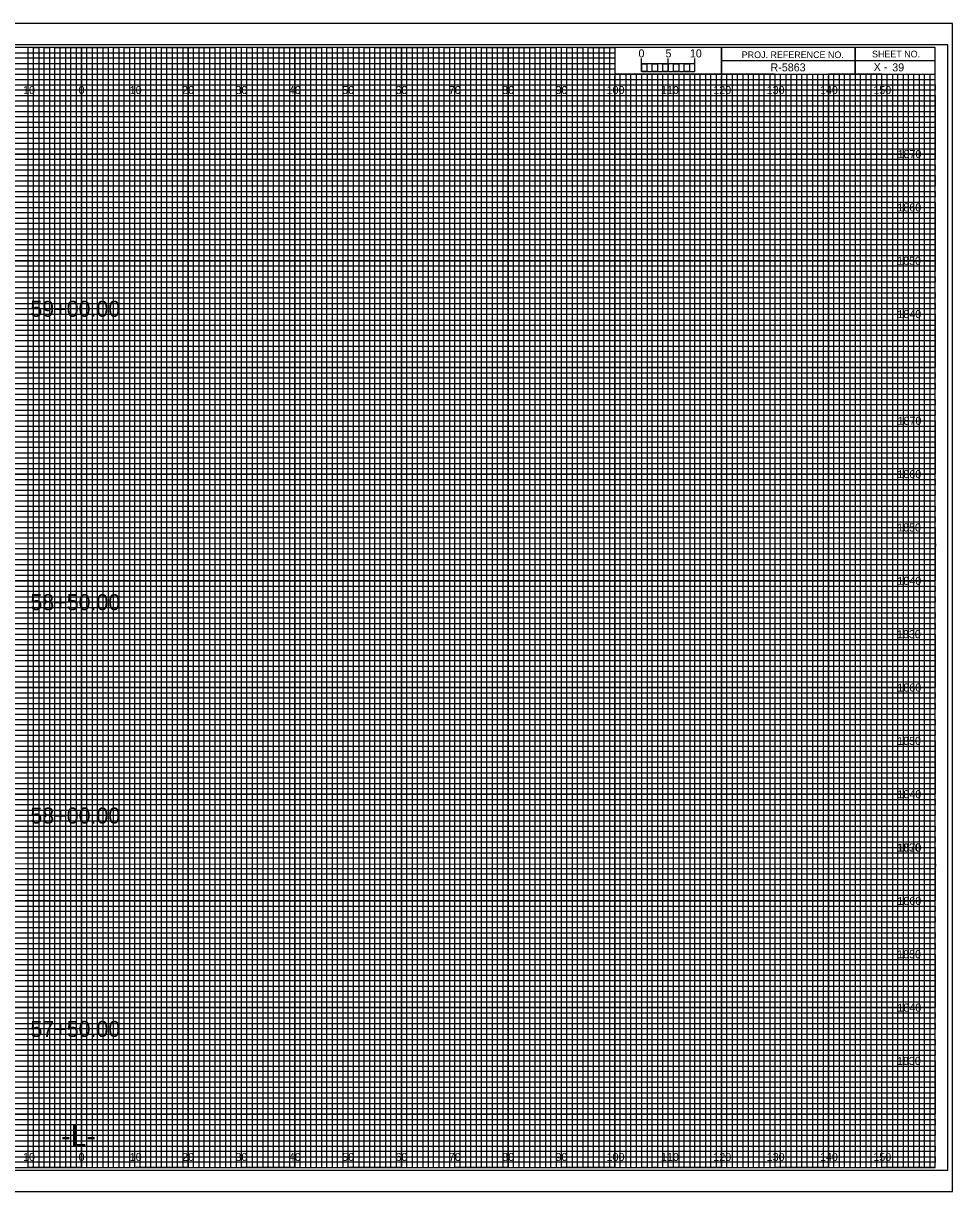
# Model space of a CAD drawing. Extents: x -13 to 323, y 8136 to 8354.
# Drawn here: x 149.1 to 323.3, y 8135.5 to 8354.5 of the extents above; entities that cross this region are included whole.
import ezdxf

# ---------------------------------------------------------------- set-up
doc = ezdxf.new("R2010")
doc.units = 0
for name, color, linetype in [('Prop XS Alignment Label', 7, 'Continuous'), ('Prop XS Bar Scale Labels', 7, 'Continuous'), ('Prop XS Elevation Labels', 7, 'Continuous'), ('Prop XS Offset Labels', 7, 'Continuous'), ('Prop XS Project Number', 7, 'Continuous'), ('Prop XS Sheet Number', 7, 'Continuous'), ('Prop XS Station Labels', 7, 'Continuous'), ('Sheet Cross Section CELL', 7, 'Continuous'), ('Sheet Cross Section Grid Major CELL', 7, 'Continuous'), ('Sheet Cross Section Grid Middle CELL', 7, 'Continuous'), ('Sheet Cross Section Grid Minor 1 CELL', 7, 'Continuous'), ('Sheet Cross Section Grid Minor 2 CELL', 7, 'Continuous'), ('Sheet Cross Section Scale CELL', 7, 'Continuous'), ('Sheet Cutting Line CELL', 7, 'Continuous'), ('Sheet DOT Grid CELL', 7, 'Continuous'), ('Sheet Plot Border Inside CELL', 7, 'Continuous'), ('Sheet Plot Border Outside CELL', 7, 'Continuous')]:
    doc.layers.add(name, color=color, linetype=linetype)

msp = doc.modelspace()

# ---------------------------------------------------------------- linework, layer by layer
at = {"layer": 'Sheet Cross Section CELL'}
for p, q in [((305, 8350), (305, 8345)), ((305, 8345), (305, 8350)), ((280, 8347.5), (280, 8345)), ((320, 8347.49), (280, 8347.49)), ((280, 8345), (320, 8345))]:
    msp.add_line(p, q, dxfattribs=at)
for points in [[(320, 8350), (0, 8350), (0, 8140), (320, 8140)], [(280, 8350), (260, 8350), (260, 8345.03), (280, 8345.03)], [(320, 8350), (280, 8350), (280, 8345), (320, 8345)]]:
    msp.add_lwpolyline(points, close=True, dxfattribs=at)
at = {"layer": 'Sheet Cross Section Grid Major CELL'}
for p, q in [((150, 8350), (140, 8350)), ((150, 8140), (150, 8350)), ((170, 8350), (160, 8350)), ((160, 8350), (160, 8140)), ((170, 8140), (170, 8350)), ((190, 8350), (180, 8350)), ((180, 8350), (180, 8140)), ((190, 8140), (190, 8350)), ((210, 8350), (200, 8350)), ((200, 8350), (200, 8140)), ((210, 8140), (210, 8350)), ((230, 8350), (220, 8350)), ((220, 8350), (220, 8140)), ((230, 8140), (230, 8350)), ((250, 8350), (240, 8350)), ((240, 8350), (240, 8140)), ((250, 8140), (250, 8350)), ((260, 8350), (260, 8140)), ((270, 8140), (270, 8345)), ((290, 8345), (280, 8345)), ((280, 8345), (280, 8140)), ((290, 8140), (290, 8345)), ((310, 8345), (300, 8345)), ((300, 8345), (300, 8140)), ((310, 8140), (310, 8345)), ((160, 8140), (150, 8140)), ((180, 8140), (170, 8140)), ((200, 8140), (190, 8140)), ((220, 8140), (210, 8140)), ((240, 8140), (230, 8140)), ((260, 8140), (250, 8140)), ((280, 8140), (270, 8140)), ((300, 8140), (290, 8140)), ((320, 8140), (310, 8140)), ((320, 8140), (320, 8140))]:
    msp.add_line(p, q, dxfattribs=at)
for points in [[(0, 8340), (320, 8340), (320, 8330), (0, 8330)], [(0, 8320), (320, 8320), (320, 8310), (0, 8310)], [(0, 8300), (320, 8300), (320, 8290), (0, 8290)], [(0, 8280), (320, 8280), (320, 8270), (0, 8270)], [(0, 8260), (320, 8260), (320, 8250), (0, 8250)], [(0, 8240), (320, 8240), (320, 8230), (0, 8230)], [(0, 8220), (320, 8220), (320, 8210), (0, 8210)], [(0, 8200), (320, 8200), (320, 8190), (0, 8190)], [(0, 8180), (320, 8180), (320, 8170), (0, 8170)], [(0, 8160), (320, 8160), (320, 8150), (0, 8150)]]:
    msp.add_lwpolyline(points, dxfattribs=at)
at = {"layer": 'Sheet Cross Section Grid Middle CELL'}
for points in [[(145, 8140), (155, 8140), (155, 8350), (165, 8350), (165, 8140), (175, 8140), (175, 8350), (185, 8350), (185, 8140), (195, 8140), (195, 8350), (205, 8350), (205, 8140), (215, 8140), (215, 8350), (225, 8350), (225, 8140), (235, 8140), (235, 8350), (245, 8350), (245, 8140), (255, 8140), (255, 8350), (259.93, 8350), (260, 8350), (260, 8345), (264.99, 8345), (264.99, 8140), (275, 8140), (275, 8345), (285, 8345), (285, 8140), (295, 8140), (295, 8345), (305, 8345), (305, 8140), (315, 8140), (315, 8345)], [(0, 8345), (275, 8345)], [(0, 8325), (320, 8325), (320, 8335), (0, 8335)], [(0, 8305), (320, 8305), (320, 8315), (0, 8315)], [(0, 8285), (320, 8285), (320, 8295), (0, 8295)], [(0, 8265), (320, 8265), (320, 8275), (0, 8275)], [(0, 8245), (320, 8245), (320, 8255), (0, 8255)], [(0, 8225), (320, 8225), (320, 8235), (0, 8235)], [(0, 8205), (320, 8205), (320, 8215), (0, 8215)], [(0, 8185), (320, 8185), (320, 8195), (0, 8195)], [(0, 8165), (320, 8165), (320, 8175), (0, 8175)], [(0, 8145), (320, 8145), (320, 8155), (0, 8155)]]:
    msp.add_lwpolyline(points, dxfattribs=at)
at = {"layer": 'Sheet Cross Section Grid Minor 1 CELL'}
for p, q in [((0, 8349), (260, 8349)), ((260, 8349), (260, 8347.98)), ((260, 8347.98), (0, 8347.98)), ((0, 8347), (260, 8347)), ((260, 8347), (260, 8345.89)), ((260, 8345.89), (0, 8345.89)), ((0, 8344), (320, 8344))]:
    msp.add_line(p, q, dxfattribs=at)
for points in [[(0, 8343), (270, 8343), (320, 8343), (320, 8342), (0, 8342)], [(0, 8341), (320, 8341), (320, 8339), (0, 8339)], [(0, 8338), (320, 8338), (320, 8337), (0, 8336.98)], [(0, 8336), (320, 8336), (320, 8334), (0, 8334)], [(0, 8333), (320, 8333), (320, 8332), (0, 8332)], [(0, 8331), (320, 8331), (320, 8329), (0, 8329)], [(0, 8328), (320, 8328), (320, 8327), (0, 8327)], [(0, 8326), (320, 8326), (320, 8324), (0, 8324)], [(0, 8323), (320, 8323), (320, 8322), (0, 8322)], [(0, 8321), (320, 8321), (320, 8319), (0, 8319)], [(0, 8318), (320, 8318), (320, 8317), (0, 8317)], [(0, 8316), (320, 8316), (320, 8313.95), (320, 8313), (320, 8312), (0, 8312)], [(0, 8314), (320, 8314), (320, 8313), (0, 8313)], [(0, 8311), (320, 8311), (320, 8309), (0, 8309.03)], [(0, 8309.03), (320, 8309), (320, 8308), (0, 8308)], [(0, 8307), (320, 8307), (320, 8306), (0, 8306)], [(0, 8304), (320, 8304), (320, 8303), (0, 8303)], [(0, 8302), (320, 8302), (320, 8301), (0, 8301)], [(-0.07, 8298.89), (320, 8298.89), (320, 8297.88), (-0.07, 8297.88)], [(0, 8297), (320, 8297), (320, 8296), (0, 8296)], [(0, 8294), (320, 8294), (320, 8293), (0, 8293)], [(0, 8292), (320, 8292), (320, 8291), (0, 8291)], [(0, 8289), (320, 8289), (320, 8288), (0, 8288)], [(0, 8287), (320, 8287), (320, 8286), (0, 8286)], [(0, 8284), (320, 8284), (320, 8283), (0, 8283)], [(0, 8282), (320, 8282), (320, 8281), (0, 8281)], [(0, 8279), (320, 8279), (319.99, 8277.98), (0, 8278)], [(0, 8277), (320, 8277), (320, 8276), (0, 8276)], [(0, 8274), (320, 8274), (320, 8273), (0, 8273)], [(0, 8272), (320, 8272), (320, 8271), (0, 8271)], [(0, 8269), (320, 8269), (320, 8268), (0, 8268)], [(0, 8267), (320, 8267), (320, 8266), (0, 8266)], [(0, 8264), (320, 8264), (320, 8263), (0, 8263)], [(0, 8262), (320, 8262), (320, 8261), (0, 8261)], [(0, 8259), (320, 8259), (320, 8258), (0, 8258)], [(0, 8256.99), (320.07, 8256.91), (320, 8256), (0, 8256)], [(0, 8254), (320, 8254), (320, 8253), (0, 8253)], [(0, 8252), (320, 8252), (320, 8251), (0, 8251)], [(0, 8249), (320, 8249), (320, 8248), (0, 8248)], [(0, 8247), (320, 8247), (320, 8246), (0, 8246)], [(0, 8244), (320, 8244), (320, 8243), (0, 8243)], [(0, 8242), (320, 8242), (320, 8241), (0, 8241)], [(0, 8239), (320, 8239), (320, 8238), (0, 8238)], [(0, 8237), (320, 8237), (320, 8236), (0, 8236)], [(0, 8234), (320, 8234), (320, 8233), (0, 8233)], [(0, 8232), (320, 8232), (320, 8231), (0, 8231)], [(0, 8229), (320, 8229), (320, 8228), (0, 8228)], [(0, 8227), (320, 8227), (320, 8226), (0, 8226)], [(0, 8224), (320, 8224), (320, 8223), (0, 8223)], [(0, 8222), (320, 8222), (320, 8221), (0, 8221)], [(0, 8219), (320, 8219), (319.99, 8217.98), (0, 8218)], [(0, 8217), (320, 8217), (320, 8216), (0, 8216)], [(0, 8214), (320, 8214), (320, 8213), (0, 8213)], [(0, 8212), (320, 8212), (320, 8211), (0, 8211)], [(0, 8209), (320, 8209), (320, 8208), (0, 8208)], [(0, 8207), (320, 8207), (320, 8206), (0, 8206)], [(0, 8204), (320, 8204), (320, 8203), (0, 8203)], [(0, 8202), (320, 8202), (320, 8201), (0, 8201)], [(0, 8199), (320, 8199), (320, 8198), (0, 8198)], [(0, 8196.99), (320.07, 8196.91), (320, 8196), (0, 8196)], [(0, 8194), (320, 8194), (320, 8193), (0, 8193)], [(0, 8192), (320, 8192), (320, 8191), (0, 8191)], [(0, 8189), (320, 8189), (320, 8188), (0, 8188)], [(0, 8187), (320, 8187), (320, 8186), (0, 8186)], [(0, 8184), (320, 8184), (320, 8183), (0, 8183)], [(0, 8182), (320, 8182), (320, 8181), (0, 8181)], [(0, 8179), (320, 8179), (320, 8178), (0, 8178)], [(0, 8177), (320, 8177), (320, 8176), (0, 8176)], [(0, 8174), (320, 8174), (320, 8173), (0, 8173)], [(0, 8172), (320, 8172), (320, 8171), (0, 8171)], [(0, 8169), (320, 8169), (320, 8168), (0, 8168)], [(0, 8167), (320, 8167), (320, 8166), (0, 8166)], [(0, 8164), (320, 8164), (320, 8163), (0, 8163)], [(0, 8162), (320, 8162), (320, 8161), (0, 8161)], [(0, 8159), (320, 8159), (320, 8158), (0, 8158)], [(0, 8157), (320, 8157), (320, 8156), (0, 8156)], [(0, 8154), (320, 8154), (320, 8153), (0, 8153)], [(0, 8152), (320, 8152), (320, 8151), (0, 8151)], [(0, 8149), (320, 8149), (320, 8148), (0, 8148)], [(0, 8147), (320, 8147), (320, 8146), (0, 8146)], [(0, 8144), (320, 8144), (320, 8143), (0, 8143)], [(0, 8142), (320, 8142), (320, 8141), (0, 8141)]]:
    msp.add_lwpolyline(points, dxfattribs=at)
at = {"layer": 'Sheet Cross Section Grid Minor 2 CELL'}
for p, q in [((267, 8345), (266.01, 8345)), ((266.01, 8345), (266.01, 8140)), ((267, 8140), (267, 8345)), ((269, 8345), (268, 8345)), ((268, 8345), (268, 8140)), ((269, 8140), (269, 8345)), ((266.01, 8140), (265, 8140)), ((268, 8140), (267, 8140))]:
    msp.add_line(p, q, dxfattribs=at)
for points in [[(150, 8140), (151, 8140), (151, 8350), (152, 8350), (152, 8140)], [(152, 8140), (153, 8140), (153, 8350), (154, 8350), (154, 8140)], [(155, 8140), (156, 8140), (156, 8350), (157, 8350), (157, 8140)], [(157, 8140), (158, 8140), (158, 8350), (159, 8350), (159, 8140)], [(160, 8140), (161, 8140), (161, 8350), (162, 8350), (162, 8140)], [(162, 8140), (163, 8140), (163, 8350), (164, 8350), (164, 8140)], [(165, 8140), (166, 8140), (166, 8350), (167, 8350), (167, 8140)], [(167, 8140), (168, 8140), (168, 8350), (169, 8350), (169, 8140)], [(170, 8140), (171, 8140), (171, 8350), (172, 8350), (172, 8140)], [(172, 8140), (173, 8140), (173, 8350), (174, 8350), (174, 8140)], [(175, 8140), (176, 8140), (176, 8350), (177, 8350), (177, 8140)], [(177, 8140), (178, 8140), (178, 8350), (179, 8350), (179, 8140)], [(180, 8140), (181, 8140), (181, 8350), (182, 8350), (182, 8140)], [(182, 8140), (183, 8140), (183, 8350), (184, 8350), (184, 8140)], [(185, 8140), (186, 8140), (186, 8350), (187, 8350), (187, 8140)], [(187, 8140), (188, 8140), (188, 8350), (189, 8350), (189, 8140)], [(190, 8140), (191, 8140), (191, 8350), (192, 8350), (192, 8140)], [(192, 8140), (193, 8140), (193, 8350), (194, 8350), (194, 8140)], [(195, 8140), (196, 8140), (196, 8350), (197, 8350), (197, 8140)], [(197, 8140), (198, 8140), (198, 8350), (199, 8350), (199, 8140)], [(200, 8140), (201, 8140), (201, 8350), (202, 8350), (202, 8140)], [(202, 8140), (203, 8140), (203, 8350), (204, 8350), (204, 8140)], [(205, 8140), (206, 8140), (206, 8350), (207, 8350), (207, 8140)], [(207, 8140), (208, 8140), (208, 8350), (209, 8350), (209, 8140)], [(210, 8140), (211, 8140), (211, 8350), (212, 8350), (212, 8140)], [(212, 8140), (213, 8140), (213, 8350), (214, 8350), (214, 8140)], [(215, 8140), (216, 8140), (216, 8350), (217, 8350), (217, 8140)], [(217, 8140), (218, 8140), (218, 8350), (219, 8350), (219, 8140)], [(220, 8140), (221, 8140), (221, 8350), (222, 8350), (222, 8140)], [(222, 8140), (223, 8140), (223, 8350), (224, 8350), (224, 8140)], [(225, 8140), (226, 8140), (226, 8350), (227, 8350), (227, 8140)], [(227, 8140), (228, 8140), (228, 8350), (229, 8350), (229, 8140)], [(230, 8140), (231, 8140), (231, 8350), (232, 8350), (232, 8140)], [(232, 8140), (233, 8140), (233, 8350), (234, 8350), (234, 8140)], [(235, 8140), (236, 8140), (236, 8350), (237, 8350), (237, 8140)], [(237, 8140), (238, 8140), (238, 8350), (239, 8350), (239, 8140)], [(240, 8140), (241, 8140), (241, 8350), (242, 8350), (242, 8140)], [(242, 8140), (243, 8140), (243, 8350), (244, 8350), (244, 8140)], [(245, 8140), (246, 8140), (246, 8350), (247, 8350), (247, 8140)], [(247, 8140), (248, 8140), (248, 8350), (249, 8350), (249, 8140)], [(250, 8140), (251, 8140), (251, 8350), (252, 8350), (252, 8140)], [(252, 8140), (253, 8140), (253, 8350), (254, 8350), (254, 8140)], [(255, 8140), (256, 8140), (256, 8350), (257, 8350), (257, 8140)], [(257, 8140), (258, 8140), (258, 8350), (259, 8350), (259, 8140)], [(260, 8140), (261, 8140), (261, 8345), (262.02, 8345), (262.02, 8140)], [(262, 8140), (263, 8140), (263, 8345), (263.99, 8345), (263.99, 8140)], [(270, 8140), (270.98, 8140), (270.98, 8345), (272, 8345), (272, 8140)], [(272, 8140), (273, 8140), (273, 8345), (274.05, 8345), (274.05, 8140)], [(275, 8140), (276, 8140), (276, 8345), (277, 8345), (277, 8140)], [(277, 8140), (278, 8140), (278, 8345), (279, 8345), (279, 8140)], [(280, 8140), (281, 8140), (281, 8345), (282, 8345), (282, 8140)], [(282, 8140), (283, 8140), (283, 8345), (284, 8345), (284, 8140)], [(285, 8140), (286, 8140), (286, 8345), (287, 8345), (287, 8140)], [(287, 8140), (288, 8140), (288, 8345), (289, 8345), (289, 8140)], [(290, 8140), (291, 8140), (291, 8345), (292, 8345), (292, 8140)], [(292, 8140), (293, 8140), (293, 8345), (294, 8345), (294, 8140)], [(295, 8140), (296, 8140), (296, 8345), (297, 8345), (297, 8140)], [(297, 8140), (298, 8140), (298, 8345), (299, 8345), (299, 8140)], [(300, 8140), (301, 8140), (301, 8345), (302, 8345), (302, 8140)], [(302, 8140), (303, 8140), (303, 8345), (304, 8345), (304, 8140)], [(305, 8140), (306, 8140), (306, 8345), (307, 8345), (307, 8140)], [(307, 8140), (308, 8140), (308, 8345), (309, 8345), (309, 8140)], [(310, 8140), (311, 8140), (311, 8345), (312, 8345), (312, 8140)], [(312, 8140), (313, 8140), (313, 8345), (314, 8345), (314, 8140)], [(315, 8140), (316, 8140), (316, 8345), (317, 8345), (317, 8140)], [(317, 8140), (318, 8140), (318, 8345), (319, 8345), (319, 8140)]]:
    msp.add_lwpolyline(points, dxfattribs=at)
at = {"layer": 'Sheet Cross Section Scale CELL'}
for p, q in [((265, 8345.49), (265, 8347.9)), ((265, 8346.9), (265, 8347.9)), ((270, 8345.49), (270, 8347.9)), ((275, 8345.49), (275, 8347.9)), ((275, 8346.9), (275, 8347.9))]:
    msp.add_line(p, q, dxfattribs=at)
for points in [[(275, 8346.9), (265, 8346.9), (265, 8345.49), (275, 8345.49)], [(265, 8346.9), (266, 8346.9), (266, 8345.49), (265, 8345.49)], [(267, 8346.9), (268, 8346.9), (268, 8345.49), (267, 8345.49)], [(269, 8346.9), (270, 8346.9), (270, 8345.49), (269, 8345.49)], [(271, 8346.9), (272, 8346.9), (272, 8345.49), (271, 8345.49)], [(273, 8346.9), (274, 8346.9), (274, 8345.49), (273, 8345.49)]]:
    msp.add_lwpolyline(points, close=True, dxfattribs=at)
at = {"layer": 'Sheet Cutting Line CELL'}
for p, q in [((323.3, 8354.5), (-13.4, 8354.5)), ((-13.4, 8135.5), (323.3, 8135.5))]:
    msp.add_line(p, q, dxfattribs=at)
at = {"layer": 'Sheet DOT Grid CELL'}
for p, q in [((150, 8140), (150, 8350)), ((160, 8140), (160, 8350)), ((170, 8140), (170, 8350)), ((180, 8140), (180, 8350)), ((190, 8140), (190, 8350)), ((200, 8140), (200, 8350)), ((210, 8140), (210, 8350)), ((220, 8140), (220, 8350)), ((230, 8140), (230, 8350)), ((240, 8140), (240, 8350)), ((250, 8140), (250, 8350)), ((260, 8140), (260, 8344.69)), ((270, 8140), (270, 8344.69)), ((280, 8140), (280, 8344.69)), ((290, 8140), (290, 8344.69)), ((300, 8140), (300, 8344.69)), ((310, 8140), (310, 8344.69)), ((0, 8340), (320, 8340)), ((0, 8330), (320, 8330)), ((0, 8320), (320, 8320)), ((0, 8310), (320, 8310)), ((0, 8300), (320, 8300)), ((0, 8290), (320, 8290)), ((0, 8280), (320, 8280)), ((0, 8270), (320, 8270)), ((0, 8260), (320, 8260)), ((0, 8250), (320, 8250)), ((0, 8240), (320, 8240)), ((0, 8230), (320, 8230)), ((0, 8220), (320, 8220)), ((0, 8210), (320, 8210)), ((0, 8200), (320, 8200)), ((0, 8190), (320, 8190)), ((0, 8180), (320, 8180)), ((0, 8170), (320, 8170)), ((0, 8160), (320, 8160)), ((0, 8150), (320, 8150))]:
    msp.add_line(p, q, dxfattribs=at)
at = {"layer": 'Sheet Plot Border Inside CELL'}
msp.add_lwpolyline([(-10.8, 8139.5), (322.4, 8139.5), (322.4, 8350.5), (-10.8, 8350.5)], close=True, dxfattribs=at)
at = {"layer": 'Sheet Plot Border Outside CELL'}
msp.add_lwpolyline([(-13.4, 8135.5), (323.3, 8135.5), (323.3, 8354.5), (-13.4, 8354.5)], close=True, dxfattribs=at)

# ---------------------------------------------------------------- texts
at = {"layer": 'Prop XS Alignment Label'}
msp.add_text('-L-', height=4, dxfattribs=at).set_placement((156.15, 8144))
at = {"layer": 'Prop XS Bar Scale Labels'}
for s, p in [('5', (269.47, 8348.12)), ('10', (274.04, 8348.12))]:
    msp.add_text(s, height=1.5, dxfattribs=at).set_placement(p)
at = {"layer": 'Prop XS Elevation Labels'}
for s, p in [('1870', (312.98, 8329.25)), ('1860', (312.95, 8319.25)), ('1850', (312.9, 8309.25)), ('1840', (312.95, 8299.25)), ('1870', (312.98, 8279.25)), ('1860', (312.95, 8269.25)), ('1850', (312.9, 8259.25)), ('1840', (312.95, 8249.25)), ('1830', (312.86, 8239.25)), ('1860', (312.95, 8229.25)), ('1850', (312.9, 8219.25)), ('1840', (312.95, 8209.25)), ('1830', (312.86, 8199.25)), ('1870', (312.98, 8199.25)), ('1860', (312.95, 8189.25)), ('1850', (312.9, 8179.25)), ('1840', (312.95, 8169.25)), ('1830', (312.86, 8159.25))]:
    msp.add_text(s, height=1.5, dxfattribs=at).set_placement(p)
at = {"layer": 'Prop XS Offset Labels'}
for s, p in [('10', (149.04, 8341.25)), ('0', (159.45, 8341.25)), ('0', (159.45, 8341.25)), ('10', (169.04, 8341.25)), ('20', (178.86, 8341.25)), ('30', (188.86, 8341.25)), ('40', (198.86, 8341.25)), ('50', (208.86, 8341.25)), ('60', (218.86, 8341.25)), ('70', (228.86, 8341.25)), ('80', (238.86, 8341.25)), ('90', (248.86, 8341.25)), ('100', (258.44, 8341.25)), ('110', (268.62, 8341.25)), ('120', (278.44, 8341.25)), ('130', (288.44, 8341.25)), ('140', (298.44, 8341.25)), ('150', (308.44, 8341.25)), ('10', (149.04, 8141.25)), ('0', (159.45, 8141.25)), ('0', (159.45, 8141.25)), ('10', (169.04, 8141.25)), ('20', (178.86, 8141.25)), ('30', (188.86, 8141.25)), ('40', (198.86, 8141.25)), ('50', (208.86, 8141.25)), ('60', (218.86, 8141.25)), ('70', (228.86, 8141.25)), ('80', (238.86, 8141.25)), ('90', (248.86, 8141.25)), ('100', (258.44, 8141.25)), ('110', (268.62, 8141.25)), ('120', (278.44, 8141.25)), ('130', (288.44, 8141.25)), ('140', (298.44, 8141.25)), ('150', (308.44, 8141.25))]:
    msp.add_text(s, height=1.5, dxfattribs=at).set_placement(p)
at = {"layer": 'Prop XS Project Number'}
msp.add_text('R-5863', height=1.5, dxfattribs=at).set_placement((289.16, 8345.5))
at = {"layer": 'Prop XS Sheet Number'}
msp.add_text('39', height=1.5, dxfattribs=at).set_placement((311.98, 8345.5))
at = {"layer": 'Prop XS Station Labels'}
for s, p in [('59+00.00', (150.41, 8299.5)), ('58+50.00', (150.41, 8244.5)), ('58+00.00', (150.41, 8204.5)), ('57+50.00', (150.41, 8164.5))]:
    msp.add_text(s, height=3, dxfattribs=at).set_placement(p)
at = {"layer": 'Sheet Cross Section CELL'}
for s, height, p in [('PROJ. REFERENCE NO.', 1.25, (283.77, 8347.99)), ('SHEET NO.', 1.25, (308.19, 8348.12)), ('X -    ', 1.5, (308.5, 8345.58))]:
    msp.add_text(s, height=height, dxfattribs=at).set_placement(p)
at = {"layer": 'Sheet Cross Section Scale CELL'}
msp.add_text('0', height=1.5, dxfattribs=at).set_placement((264.41, 8348.12))

doc.saveas('drawing.dxf')
